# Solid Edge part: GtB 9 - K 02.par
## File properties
Author: Carsten
Template: Normal.par
Last saved by: Carsten
Revision: 4
Application: Solid Edge
Genauigkeit: 0,990
Teilflächenrmatvorlage: Model Default
Coef. of Thermal Exp: 0.0
Thermal Conductivity: 0.0
Specific Heat: 0.0
Modulus of Elasticity: 0.0
Poission's Ratio: 0.0
Yield Stress: 0.0
Ultimate Stress: 0.0
Elongation: 0.0
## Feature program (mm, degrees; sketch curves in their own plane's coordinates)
sketch for "unnamed Protrusion 1" plane through (0, 0, 0) normal (0, -1, 0) x-axis (1, 0, 0)
  line (-14.5004, -27.5374) -> (60.4996, -27.5374)
  line (60.4996, -27.5374) -> (60.4996, 92.4626)
  line (60.4996, 92.4626) -> (-14.5004, 92.4626)
  line (-14.5004, 92.4626) -> (-14.5004, -27.5374)
extrude "unnamed Protrusion 1" add finite 55 along -normal
sketch for "Ausprägung_2" #1 plane through (22.9996, 0, 32.4626) normal (0, -1, 0) x-axis (1, 0, 0)
  line (37.5, -60) -> (37.5, -25)
  line (12.5, -60) -> (37.5, -25)
  line (37.5, -60) -> (12.5, -60)
sketch for "Ausprägung_2" #2 plane through (22.9996, 0, 32.4626) normal (0, -1, 0) x-axis (1, 0, 0)
  line (-17.5, 10) -> (-17.5, -25)
  line (-17.5, -25) -> (27.5, -25)
  line (27.5, -25) -> (27.5, 10)
  line (27.5, 10) -> (-17.5, 10)
sketch for "Ausprägung_2" #3 plane through (22.9996, 0, 32.4626) normal (0, -1, 0) x-axis (1, 0, 0)
  line (-37.5, 60) -> (-12.5, 60)
  line (-12.5, 60) -> (-12.5, 25)
  line (-12.5, 25) -> (-37.5, 25)
  line (-37.5, 25) -> (-37.5, 60)
extrude "Ausprägung_2" add finite 111.125 along -normal
sketch for "Ausschnitt_1" #1 plane through (22.9996, 55, 32.4626) normal (0, 1, 0) x-axis (-1, 0, 0)
  line (12.5, 25) -> (37.5, 25)
  line (37.5, 25) -> (37.5, 60)
  line (12.5, 60) -> (37.5, 60)
  line (12.5, 25) -> (12.5, 60)
sketch for "Ausschnitt_1" #2 plane through (22.9996, 55, 32.4626) normal (0, 1, 0) x-axis (-1, 0, 0)
  line (-27.5, 10) -> (-27.5, -25)
  line (-27.5, -25) -> (17.5, -25)
  line (17.5, -25) -> (17.5, 10)
  line (17.5, 10) -> (-27.5, 10)
sketch for "Ausschnitt_1" #3 plane through (22.9996, 55, 32.4626) normal (0, 1, 0) x-axis (-1, 0, 0)
  line (-37.5, -60) -> (-12.5, -60)
  line (-37.5, -25) -> (-12.5, -60)
  line (-37.5, -60) -> (-37.5, -25)
extrude "Ausschnitt_1" cut finite 882.65 symmetric
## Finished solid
Body 1: solid body, 13 faces, 33 edges, 22 vertices.
  Faces by surface: plane 13
  Edges by curve: line 33
Bounding box of the edges (mm): 75.000 x 55.000 x 120.000, from (-14.5004, 0, -27.5374) to (60.4996, 55, 92.4626).
Planar faces by outward normal: +x 2, +y 1, +z 3, -x 3, -y 1, -z 2, oblique 1
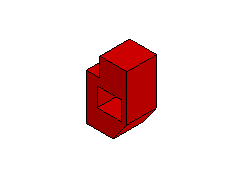
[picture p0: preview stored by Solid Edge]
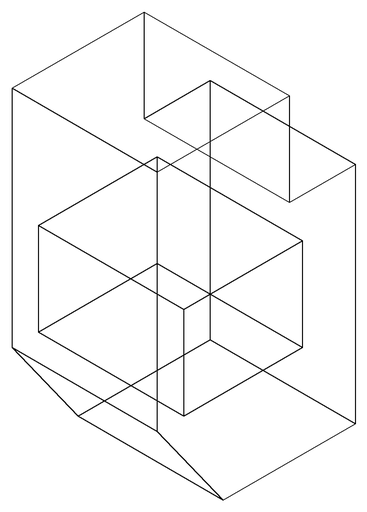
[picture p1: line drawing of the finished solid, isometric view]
